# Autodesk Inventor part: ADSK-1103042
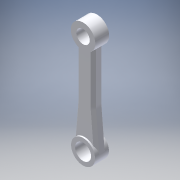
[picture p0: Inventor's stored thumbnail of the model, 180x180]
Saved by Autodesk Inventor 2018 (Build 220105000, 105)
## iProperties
Shininess: 50.0
Length Units: 11272
Angle Units: 11279
Time Units: 11290
Mass Units: 11286
Length Display Precision: 4
Angle Display Precision: 2
Compacted: True
Created: 2000-11
Part Number: ADSK-1103042
Document SubType Name: Modeling
Description: CONNECTING ROD
Mass: 0.815863 g
Surface Area: 4.69105 cm^2
Volume: 0.301057 cm^3
Density: 2.71 g/cm^3
Material: Aluminum-6061
Appearance: Aluminum - Flat
Density: 0.0
Volumn: 0.0
Area: 0.0
PropertySet Name: Model Information
Control State: 0
Master: False
Checked Out: False
Author: Autodesk, Inc.
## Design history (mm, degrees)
node "Extrusion1" dims "d8" = 2.54, "d9" = 0
  sketch "Sketch2"
    geometry: L1 (-7.585, -9.592)-(-6.801, -0.307); L2 (-6.801, -0.307)-(-6.801, 11.849); L3 (-2.674, 11.849)-(-2.674, -0.307); L4 (-2.674, -0.307)-(-1.89, -9.592); C1 r 1.905 at (-4.737, -9.832); C2 r 1.587 at (-4.737, 13.917); C3 r 2.064 at (-4.737, 13.917); A1 r 2.857 centre (-4.737, -9.832) between (-7.585, -9.592) and (-1.89, -9.592); A2 r 2.921 centre (-4.737, 13.917) between (-2.674, 11.849) and (-6.801, 11.849)
    constraints: 8 end point, 5 centre point, 4 point on circle, 4 tangent, 2 coincident, 1 concentric, 1 horizontal alignment, 1 parallel, 1 vertical, 1 vertical alignment, 1 other
    dimensions: "d0" = 3.81 diameter of C1; "d1" = 3.175 diameter of C2; "d2" = 23.749 distance of C1.centre C2.centre; "d3" = 4.1275 diameter of C3; "d5" = 5.715 diameter of A1; "d7" = 9.525 vertical distance of L1.end C1.centre; "d17" = 2.921 radius of A2
node "Extrusion2" dims "d10" = 0.381, "d11" = 0
  sketch "Sketch3"
    geometry: L1 (6.801, -0.307)-(7.585, -9.592) reference; C1 r 1.587 at (4.737, 13.917) reference; C2 r 2.858 at (4.737, -9.832); A1 r 2.857 centre (4.737, -9.832) between (1.89, -9.592) and (7.585, -9.592) reference; A2 r 2.921 centre (4.737, 13.917) between (6.801, 11.849) and (2.674, 11.849) reference; 3 further points
    constraints: 2 coincident, 1 centre point, 1 tangent, 5 other
node "Extrusion3" dims "d12" = 0.381, "d13" = 0
  sketch "Sketch4"
    geometry: A1 r 2.857 centre (-4.737, -9.832) between (-7.585, -9.592) and (-1.89, -9.592) reference; A2 r 2.921 centre (-4.737, 13.917) between (-2.674, 11.849) and (-6.801, 11.849) reference; 6 further points
    constraints: 2 coincident, 10 other
node "Fillet1" dims "d14" = 8.001
node "Chamfer1" dims "d15" = 0.635, "d16" = 0.635, "d18" = 45 deg
workplane "Work Plane1"
body "Solid1"
